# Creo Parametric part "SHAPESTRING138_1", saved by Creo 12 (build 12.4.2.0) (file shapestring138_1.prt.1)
Units: Custom; MM, KILOGRAM, SECS

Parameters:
  PTC_WM_ITERATION = "0"
  PTC_WM_VERSION = "-.0"
  PTC_WM_LIFECYCLE_STATE = "In Work"
  PTC_WM_LIFECYCLE = "MO_CADDocument"
  PTC_WM_CREATED_BY = "Maximilian Roepper (Z0017RMS: MO)"
  PTC_WM_CREATED_ON = "18-Sep-26 11:36:42 AM"
  PTC_WM_MODIFIED_BY = "Maximilian Roepper (Z0017RMS: MO)"
  PTC_WM_MODIFIED_ON = "18-Sep-26 11:36:46 AM"
  PDMLINKNUMBER = "PDM000071454891"
  PTC_WM_NAME = "shapestring138_1.prt"
  PTC_WM_NUMBER = "PDM000071454891"

Other parameters: WEIGHT, WEIGHT_FACTOR, WEIGHT_ADD, _MASS_TEMP, _DIFF_TEMP, MC_ERRORS, SUPPLIER

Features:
  1. coordinate system
  2. datum plane "PRT_YZ"
  3. datum plane "PRT_XY"
  4. datum plane "PRT_XZ"
  5. coordinate system
  6. datum axis
  7. datum axis
  8. datum axis
  9. coordinate system
  10. imported feature
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
Other named items: PRT, SIEMENS_MO, DRW_VIEW_ORG, PRT_X, PRT_Y, PRT_Z, CS0, ROUGH_GROB

Layers: 00_STD_CSYS-KSYS, 01_STD_PLANES-EBENEN, 02_STD_AXES-ACHSEN, 03_STD_CSYS-KSYS, 24_IMPORT_FEAT-IMPORT_KE, INTFCLR

Surfaces: 1 plane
